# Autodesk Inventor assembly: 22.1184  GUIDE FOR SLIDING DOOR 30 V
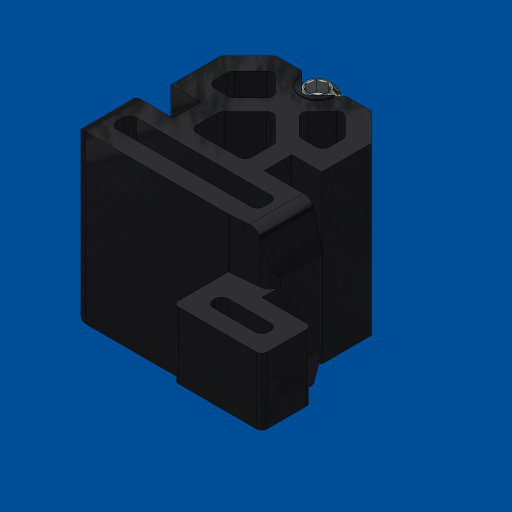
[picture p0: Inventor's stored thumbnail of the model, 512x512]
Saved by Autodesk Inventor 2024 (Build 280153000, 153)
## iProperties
Created: 2024-12
Part Number: 22.1184  GUIDE FOR SLIDING DOOR 30 V
Document SubType Name: Assembly
Designer: amoles
Author: amoles
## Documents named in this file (3)
- L:\INVENTOR LIBRARIES\PARTS LIBRARY\30 SERIES\22.1184  GUIDE FOR SLIDING DOOR 30 V.iam
- L:\INVENTOR LIBRARIES\PARTS LIBRARY\30 SERIES\SUBCOMPONENTS\22.1184_1.ipt
- L:\INVENTOR LIBRARIES\PARTS LIBRARY\30 SERIES\SUBCOMPONENTS\22.1184 M3X6 DOG POINT SET SCREW.ipt
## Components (2 placed, 2 different names)
1. 22.1184_1:1 — Mate:1, Mate:2, Flush:1, Mate:3, Angle:1, Flush:2
2. 22.1184 M3X6 DOG POINT SET SCREW:1 — Mate:3, Angle:1, Flush:2
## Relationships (6: Mate 3, Flush 2, Angle 1)
- Mate:1: 22.1184_1:1
- Mate:2: 22.1184_1:1
- Flush:1: 22.1184_1:1
- Mate:3: 22.1184_1:1 ↔ 22.1184 M3X6 DOG POINT SET SCREW:1
- Angle:1: 22.1184_1:1 ↔ 22.1184 M3X6 DOG POINT SET SCREW:1
- Flush:2: 22.1184_1:1 ↔ 22.1184 M3X6 DOG POINT SET SCREW:1
